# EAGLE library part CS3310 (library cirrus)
Stereo Digital Volume Control 2 Channels, Serial Control
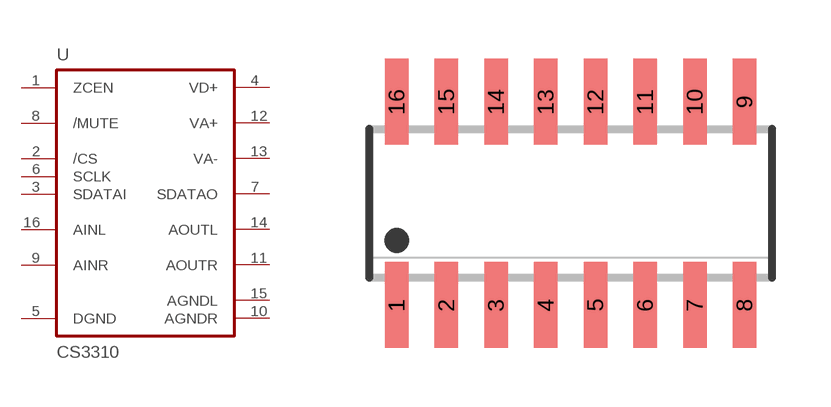
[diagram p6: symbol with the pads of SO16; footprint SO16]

Designator prefix U

## CS3310  [SO16]
1  ZCEN  in
2  /CS  in
3  SDATAI  in
4  VD+  pwr
5  DGND  pwr
6  SCLK  in
7  SDATAO  out
8  /MUTE  in
9  AINR  in
10  AGNDR  pas
11  AOUTR  out
12  VA+  pwr
13  VA-  pwr
14  AOUTL  out
15  AGNDL  pas
16  AINL  in

## Footprint SO16 (pad centres in mm)
SMALL OUTLINE INTEGRATED CIRCUIT body 3.9 mm/JEDEC MS-012AC
smd 0.6 x 2.2: 1 -4.445,-2.6; 2 -3.175,-2.6; 3 -1.905,-2.6; 4 -0.635,-2.6; 5 0.635,-2.6; 6 1.905,-2.6; 7 3.175,-2.6; 8 4.445,-2.6; 9 4.445,2.6; 10 3.175,2.6; 11 1.905,2.6; 12 0.635,2.6; 13 -0.635,2.6; 14 -1.905,2.6; 15 -3.175,2.6; 16 -4.445,2.6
